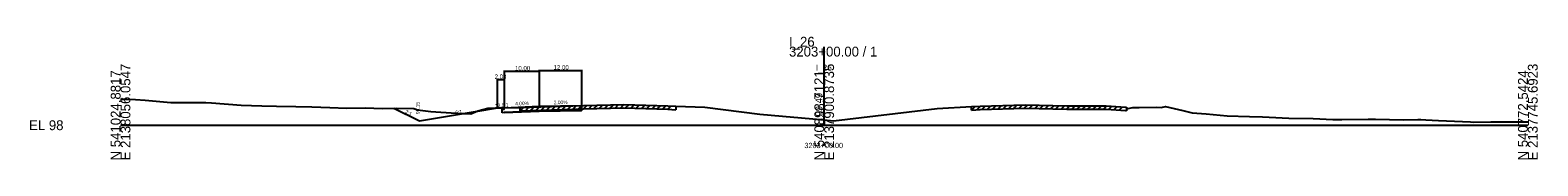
# Model space of a CAD drawing. Extents: x -13101 to 4803, y -924 to 22390.
# Drawn here: x 1974.3 to 2402.8, y 1490.3 to 1525.2 of the extents above; entities that cross this region are included whole.
import ezdxf

# ---------------------------------------------------------------- set-up
doc = ezdxf.new("R2010")
doc.units = 0
for name, color, linetype in [('RD_GPK_XS_Cell', 7, 'Continuous'), ('RD_XD_TX_Width', 7, 'Continuous'), ('RD_XS_Base', 7, 'Continuous'), ('RD_XS_EarthShd', 7, 'Continuous'), ('RD_XS_EwShp', 7, 'Continuous'), ('RD_XS_ExGround', 7, 'Continuous'), ('RD_XS_ExPaveRet', 7, 'Continuous'), ('RD_XS_OSBase', 7, 'Continuous'), ('RD_XS_Pave', 7, 'Continuous'), ('RD_XS_TieSlope', 7, 'Continuous'), ('RD_XS_TX_Baseline', 7, 'Continuous'), ('RD_XS_TX_Elev_EX', 7, 'Continuous'), ('RD_XS_TX_Elev_PR', 7, 'Continuous'), ('RD_XS_TX_ShdSlope', 7, 'Continuous'), ('RD_XS_TX_Slope', 7, 'Continuous'), ('RD_XS_TX_Station', 7, 'Continuous')]:
    doc.layers.add(name, color=color, linetype=linetype)

msp = doc.modelspace()

# ---------------------------------------------------------------- linework, layer by layer
at = {"layer": 'RD_GPK_XS_Cell'}
for p, q in [((2200, 1500), (2200, 1522.32)), ((2000, 1500), (2200, 1500)), ((2200, 1500), (2400, 1500))]:
    msp.add_line(p, q, dxfattribs=at)
at = {"layer": 'RD_XD_TX_Width'}
for p, q in [((2107, 1513.13), (2107, 1505.02)), ((2109, 1512.93), (2107, 1512.93)), ((2109, 1515.53), (2109, 1505.18)), ((2109, 1515.33), (2119, 1515.33)), ((2109, 1513.13), (2109, 1505.18)), ((2119, 1515.77), (2119, 1505.58)), ((2119, 1515.57), (2131, 1515.57)), ((2119, 1515.53), (2119, 1505.58)), ((2131, 1515.77), (2131, 1505.82))]:
    msp.add_line(p, q, dxfattribs=at)
at = {"layer": 'RD_XS_Base'}
for p, q in [((2119, 1503.98), (2131, 1504.22)), ((2109, 1503.58), (2119, 1503.98))]:
    msp.add_line(p, q, dxfattribs=at)
at = {"layer": 'RD_XS_EarthShd'}
msp.add_line((2109, 1504.98), (2107, 1504.82), dxfattribs=at)
at = {"layer": 'RD_XS_EwShp'}
for points in [[(2095.4, 1503.44), (2098.02, 1503.32), (2085, 1501.15), (2077.72, 1504.79), (2078.47, 1504.8), (2083.36, 1504.79), (2083.89, 1504.53), (2084.36, 1504.34), (2088.19, 1503.93)], [(2100.92, 1503.81), (2101.58, 1504.07), (2104.38, 1504.8), (2108.8, 1504.96), (2107, 1504.82)], [(2108.5, 1503.56), (2108.5, 1504.56), (2109, 1504.58), (2109, 1504.98), (2111.9, 1505.06), (2113.43, 1505.08), (2119.49, 1505.26), (2131, 1505.62), (2131, 1505.22), (2131, 1504.22), (2119, 1503.98), (2109, 1503.58)], [(2108.8, 1504.96), (2108.91, 1504.97), (2109, 1504.98)], [(2099.53, 1503.25), (2100.92, 1503.81), (2098.02, 1503.32)]]:
    msp.add_lwpolyline(points, close=True, dxfattribs=at)
at = {"layer": 'RD_XS_ExGround'}
msp.add_lwpolyline([(2000, 1507.44), (2001.81, 1507.39), (2004.28, 1507.3), (2006.96, 1507.09), (2014.29, 1506.49), (2023.23, 1506.41), (2024.25, 1506.42), (2025.82, 1506.32), (2034.31, 1505.7), (2040.16, 1505.52), (2044.32, 1505.44), (2049.85, 1505.29), (2054.33, 1505.23), (2059.48, 1505.08), (2064.34, 1504.88), (2069.67, 1504.92), (2074.35, 1504.76), (2078.47, 1504.8), (2083.36, 1504.79), (2083.89, 1504.53), (2084.36, 1504.34), (2088.19, 1503.93), (2095.4, 1503.44), (2099.53, 1503.25), (2101.58, 1504.07), (2104.38, 1504.8), (2108.91, 1504.97), (2111.9, 1505.06), (2113.43, 1505.08), (2119.49, 1505.26), (2131.56, 1505.64), (2143.08, 1505.92), (2155.56, 1505.53), (2157.84, 1505.38), (2166.04, 1505.1), (2181.73, 1503.15), (2200, 1501.49), (2202.66, 1501.25), (2232.08, 1504.75), (2241.85, 1505.28), (2244.32, 1505.42), (2257.11, 1505.83), (2268.94, 1505.54), (2280.17, 1505.55), (2285.77, 1505.17), (2286.41, 1504.78), (2287.21, 1504.9), (2287.72, 1505.07), (2289.54, 1505.04), (2294.56, 1505.11), (2295.81, 1505.08), (2297.04, 1505.29), (2301.92, 1504.15), (2304.57, 1503.56), (2308.56, 1503.22), (2314.58, 1502.67), (2320.9, 1502.49), (2324.59, 1502.4), (2326.49, 1502.28), (2332.09, 1502.04), (2338.97, 1501.87), (2344.61, 1501.66), (2347.1, 1501.63), (2354.62, 1501.69), (2356.7, 1501.68), (2364.63, 1501.53), (2368.71, 1501.61), (2369.58, 1501.63), (2370.98, 1501.54), (2374.64, 1501.3), (2383.73, 1500.95), (2384.65, 1500.91), (2389.45, 1500.96), (2400, 1500.93)], dxfattribs=at)
at = {"layer": 'RD_XS_ExPaveRet'}
for p, q in [((2113.56, 1504.08), (2114.59, 1505.11)), ((2113.56, 1504.08), (2113.56, 1505.08)), ((2113.56, 1504.08), (2119.49, 1504.26)), ((2115.06, 1504.12), (2116.09, 1505.16)), ((2116.56, 1504.17), (2117.59, 1505.2)), ((2118.06, 1504.22), (2119.09, 1505.25)), ((2119.49, 1504.26), (2131.56, 1504.64)), ((2119.56, 1504.26), (2120.59, 1505.29)), ((2121.06, 1504.31), (2122.09, 1505.34)), ((2122.56, 1504.35), (2123.59, 1505.39)), ((2124.06, 1504.4), (2125.09, 1505.43)), ((2125.56, 1504.45), (2126.59, 1505.48)), ((2127.06, 1504.5), (2128.09, 1505.53)), ((2128.56, 1504.54), (2129.59, 1505.57)), ((2130.06, 1504.59), (2131.09, 1505.62)), ((2131.56, 1504.64), (2132.58, 1505.66)), ((2131.56, 1504.64), (2143.08, 1504.92)), ((2133.06, 1504.67), (2134.08, 1505.7)), ((2134.56, 1504.71), (2135.58, 1505.73)), ((2136.06, 1504.75), (2137.08, 1505.77)), ((2137.56, 1504.78), (2138.58, 1505.81)), ((2139.06, 1504.82), (2140.08, 1505.84)), ((2140.56, 1504.86), (2141.58, 1505.88)), ((2142.06, 1504.89), (2143.08, 1505.92)), ((2143.08, 1504.92), (2155.56, 1504.53)), ((2143.56, 1504.9), (2144.53, 1505.87)), ((2145.06, 1504.86), (2146.03, 1505.83)), ((2146.56, 1504.81), (2147.53, 1505.78)), ((2148.06, 1504.76), (2149.03, 1505.73)), ((2149.56, 1504.72), (2150.53, 1505.68)), ((2151.06, 1504.67), (2152.03, 1505.64)), ((2152.56, 1504.62), (2153.53, 1505.59)), ((2154.06, 1504.57), (2155.03, 1505.54)), ((2155.56, 1504.53), (2156.49, 1505.47)), ((2155.56, 1504.53), (2157.84, 1504.38)), ((2157.84, 1505.38), (2157.84, 1504.38)), ((2241.85, 1504.28), (2242.91, 1505.34)), ((2241.85, 1504.28), (2241.85, 1505.28)), ((2241.85, 1504.28), (2244.32, 1504.42)), ((2243.35, 1504.37), (2244.4, 1505.42)), ((2244.32, 1504.42), (2257.11, 1504.83)), ((2244.85, 1504.44), (2245.88, 1505.47)), ((2246.35, 1504.49), (2247.38, 1505.52)), ((2247.85, 1504.53), (2248.88, 1505.57)), ((2249.35, 1504.58), (2250.38, 1505.61)), ((2250.85, 1504.63), (2251.88, 1505.66)), ((2252.35, 1504.68), (2253.38, 1505.71)), ((2253.85, 1504.72), (2254.88, 1505.76)), ((2255.35, 1504.77), (2256.38, 1505.8)), ((2256.85, 1504.82), (2257.84, 1505.81)), ((2257.11, 1504.83), (2268.94, 1504.54)), ((2258.35, 1504.8), (2259.32, 1505.77)), ((2259.85, 1504.76), (2260.82, 1505.74)), ((2261.35, 1504.72), (2262.32, 1505.7)), ((2262.85, 1504.69), (2263.82, 1505.66)), ((2264.35, 1504.65), (2265.32, 1505.63)), ((2265.85, 1504.61), (2266.82, 1505.59)), ((2267.35, 1504.58), (2268.32, 1505.55)), ((2268.85, 1504.54), (2269.84, 1505.54)), ((2268.94, 1504.54), (2280.17, 1504.55)), ((2270.35, 1504.54), (2271.35, 1505.54)), ((2271.85, 1504.54), (2272.85, 1505.54)), ((2273.35, 1504.54), (2274.35, 1505.54)), ((2274.85, 1504.54), (2275.85, 1505.54)), ((2276.35, 1504.54), (2277.35, 1505.54)), ((2277.85, 1504.54), (2278.85, 1505.55)), ((2279.35, 1504.55), (2280.34, 1505.54)), ((2280.17, 1504.55), (2285.77, 1504.17)), ((2280.85, 1504.5), (2281.78, 1505.44)), ((2282.35, 1504.4), (2283.28, 1505.34)), ((2283.85, 1504.3), (2284.78, 1505.24)), ((2285.77, 1504.17), (2285.92, 1504.08)), ((2285.92, 1505.08), (2285.92, 1504.08))]:
    msp.add_line(p, q, dxfattribs=at)
at = {"layer": 'RD_XS_OSBase'}
for p, q in [((2108.5, 1504.56), (2109, 1504.58)), ((2108.5, 1503.56), (2108.5, 1504.56)), ((2109, 1504.58), (2109, 1504.98)), ((2131, 1505.22), (2131, 1505.62)), ((2131, 1504.22), (2131, 1505.22)), ((2109, 1503.58), (2108.5, 1503.56))]:
    msp.add_line(p, q, dxfattribs=at)
at = {"layer": 'RD_XS_Pave'}
for p, q in [((2109, 1504.98), (2119, 1505.38)), ((2119, 1505.38), (2131, 1505.62))]:
    msp.add_line(p, q, dxfattribs=at)
at = {"layer": 'RD_XS_TieSlope'}
for p, q in [((2085, 1501.15), (2077.72, 1504.79)), ((2107, 1504.82), (2085, 1501.15))]:
    msp.add_line(p, q, dxfattribs=at)

# ---------------------------------------------------------------- texts
at = {"layer": 'RD_GPK_XS_Cell'}
for s, p in [('3203+00.00 / 1', (2190, 1519.52)), ('I_26', (2190, 1522.32)), ('EL 98', (1974, 1498.6))]:
    msp.add_text(s, height=2.8, dxfattribs=at).set_placement(p)
for s, p in [('E 2138056.0547', (2002.8, 1490)), ('E 2137900.8735', (2202.8, 1490)), ('E 2137745.6923', (2402.8, 1490)), ('N 541024.8817', (2000, 1490)), ('N 540898.7121', (2200, 1490)), ('N 540772.5424', (2400, 1490))]:
    msp.add_text(s, height=2.8, rotation=90, dxfattribs=at).set_placement(p)
at = {"layer": 'RD_XD_TX_Width'}
for s, p in [('12.00', (2123.07, 1515.82)), ('2.00', (2106.31, 1513.18)), ('10.00', (2112.11, 1515.58))]:
    msp.add_text(s, height=1.25, dxfattribs=at).set_placement(p)
at = {"layer": 'RD_XS_TX_Baseline'}
msp.add_text('I_26', height=1.75, dxfattribs=at).set_placement((2197.6, 1515.49))
at = {"layer": 'RD_XS_TX_Elev_EX'}
msp.add_text('99.49', height=2, rotation=90, dxfattribs=at).set_placement((2199.5, 1502.49))
at = {"layer": 'RD_XS_TX_Elev_PR'}
msp.add_text('99.15', height=1, rotation=90, dxfattribs=at).set_placement((2085, 1503.15))
at = {"layer": 'RD_XS_TX_ShdSlope'}
msp.add_text('12.5:1', height=1, rotation=4.5739, dxfattribs=at).set_placement((2106.47, 1505.03))
msp.add_text('12.5:1', height=1, rotation=4.5739, dxfattribs=at).set_placement((2106.47, 1505.03))
at = {"layer": 'RD_XS_TX_Slope'}
for s, rotation, p in [('2:1', 333.4349, (2080.8, 1503.53)), ('6:1', 9.4623, (2095.26, 1503.12)), ('4.00%', 2.2906, (2112.18, 1505.61)), ('2.00%', 1.1458, (2123.14, 1505.96))]:
    msp.add_text(s, height=1, rotation=rotation, dxfattribs=at).set_placement(p)
at = {"layer": 'RD_XS_TX_Station'}
msp.add_text('3203+00.00', height=1.5, dxfattribs=at).set_placement((2194.37, 1493.49))

doc.saveas('drawing.dxf')
